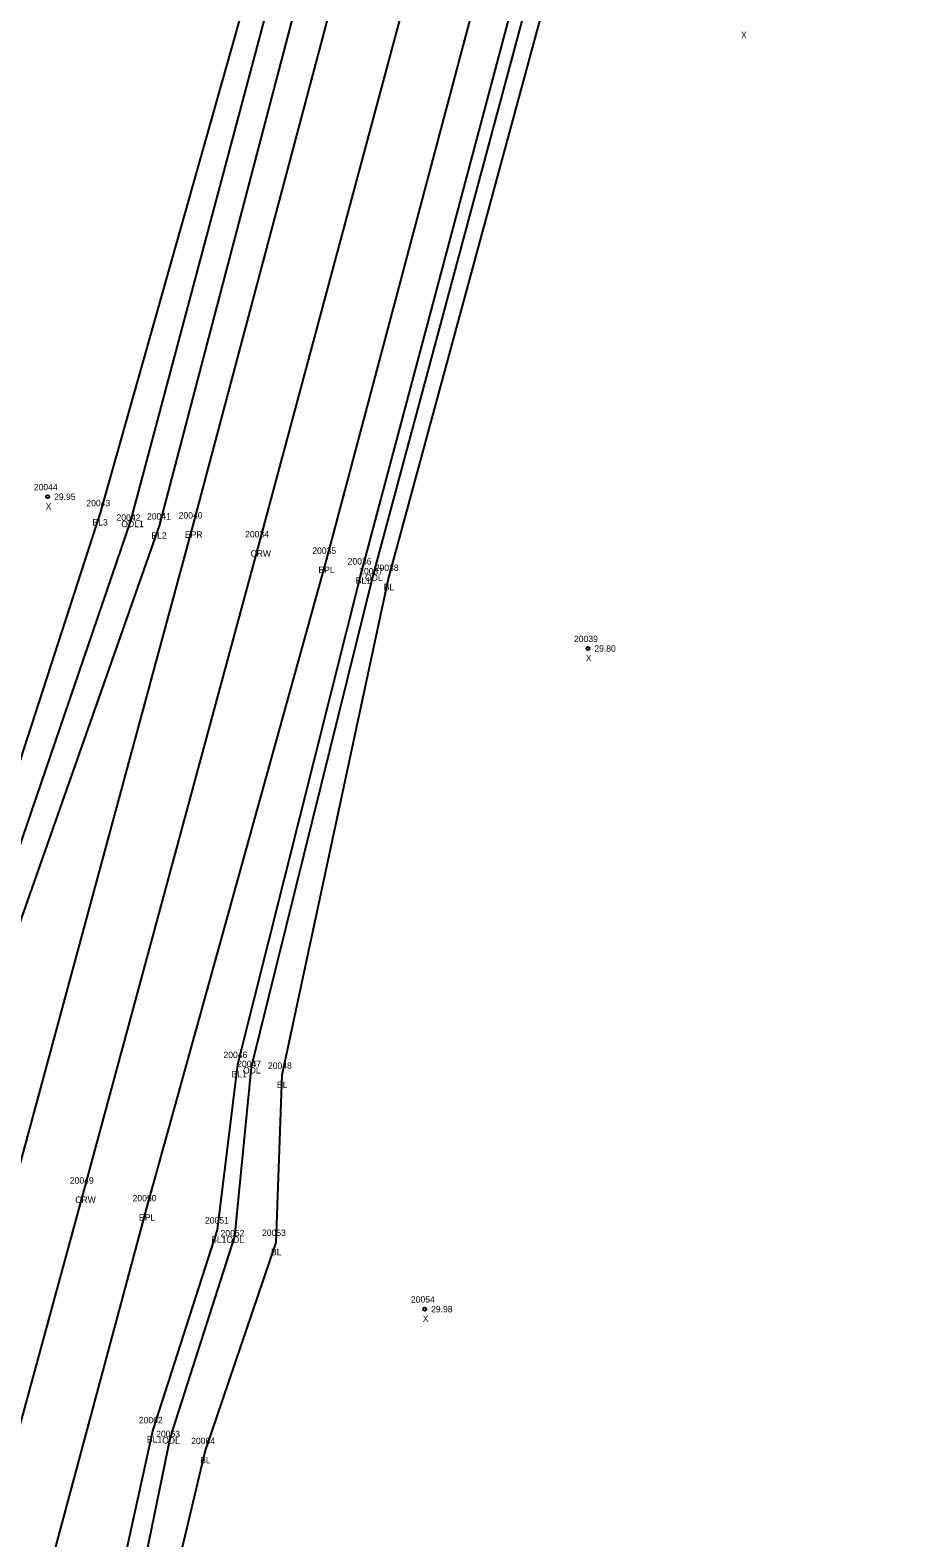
# Model space of a CAD drawing. Extents: x 2432729 to 2433340, y 684958 to 688103.
# Drawn here: x 2433024.5 to 2433161.1, y 687632.9 to 687867.9 of the extents above; entities that cross this region are included whole.
import ezdxf

# ---------------------------------------------------------------- set-up
doc = ezdxf.new("R2010")
doc.units = 0
for name, color, linetype in [('RD_DTM_BkLn1', 7, 'Continuous'), ('RD_EX_H2O', 7, 'Continuous'), ('RD_EX_H2O_txCode', 7, 'Continuous'), ('RD_EX_Road', 7, 'Continuous'), ('RD_EX_Road_txCode', 7, 'Continuous'), ('RD_Sketch8', 7, 'Continuous'), ('RD_SMD_Locator', 7, 'Continuous'), ('RD_SMD_Misc', 7, 'Continuous')]:
    doc.layers.add(name, color=color, linetype=linetype)

msp = doc.modelspace()

# ---------------------------------------------------------------- linework, layer by layer
at = {"layer": 'RD_DTM_BkLn1'}
for points in [[(2433118.26, 688093.2), (2433092.06, 687992.21), (2433063.59, 687892.57), (2433035.4, 687792.67), (2433003.26, 687693.63), (2432973.78, 687591.87), (2432942.45, 687477.63), (2432922.14, 687395), (2432910.39, 687336.67), (2432899.1, 687275.13), (2432892.65, 687218), (2432891.75, 687172.49)], [(2433125.46, 688091.48), (2433098.1, 687989.98), (2433070.67, 687890.07), (2433044.57, 687790.6), (2433009.89, 687691.98), (2432980.82, 687589.28), (2432951.34, 687483.95), (2432927.37, 687394.4), (2432914.6, 687336.1), (2432907.58, 687275.27), (2432904.68, 687217.27), (2432900.37, 687172.96), (2432891.75, 687172.49)], [(2433140.82, 688087.65), (2433112.94, 687984.39), (2433086.23, 687884.97), (2433060.15, 687787.81), (2433032.83, 687687.07), (2433004.93, 687584.9), (2432976.21, 687475.71), (2432953.67, 687387.58), (2432941.78, 687332.31), (2432932.37, 687274.14), (2432926.02, 687213.66), (2432924.35, 687158.94)], [(2433156.54, 688084.3), (2433128.42, 687980.72), (2433101.84, 687880.23), (2433076.15, 687783.58), (2433056.79, 687706.65), (2433053.61, 687680.85), (2433043.6, 687649.71), (2433027.96, 687578.58), (2432999.4, 687470.47), (2432976.82, 687380.76), (2432967.08, 687327.52), (2432956.82, 687270.44), (2432953.12, 687234.52), (2432952.13, 687211.69)], [(2433161.14, 688083.06), (2433133.45, 687979.3), (2433106.44, 687878.75), (2433080.34, 687782.58), (2433063.71, 687704.97), (2433062.78, 687678.91), (2433051.75, 687646.46), (2433035.42, 687577.73), (2433004.6, 687469.86), (2432982.67, 687378.73), (2432971.98, 687326.06), (2432962.83, 687268.71), (2432961.78, 687241.18), (2432987.4, 687248.62)]]:
    msp.add_lwpolyline(points, dxfattribs=at)
at = {"layer": 'RD_EX_H2O'}
for points in [[(2433122.48, 688092.22), (2433094.03, 687991.07), (2433066.93, 687892.02), (2433040.1, 687791.41), (2433006.23, 687692.29), (2432977.32, 687590.19), (2432946.52, 687480.52), (2432925.1, 687394.47), (2432912.11, 687336.21), (2432903.51, 687275.66), (2432898.99, 687217.48), (2432895.84, 687179.01)], [(2433158.82, 688083.82), (2433130.6, 687980.05), (2433103.89, 687879.65), (2433077.93, 687783.05), (2433058.91, 687706.24), (2433056.32, 687679.85), (2433046.3, 687648.55), (2433031.84, 687578.12), (2433002.04, 687470.32), (2432979.46, 687380.11), (2432969.67, 687326.76), (2432959.16, 687269.46), (2432956.03, 687234.5)]]:
    msp.add_lwpolyline(points, dxfattribs=at)
at = {"layer": 'RD_EX_Road'}
for points in [[(2433130.63, 688090.22), (2433103.18, 687988.73), (2433075.68, 687887.89), (2433049.83, 687790.75), (2433022.33, 687689.17), (2432994.76, 687586.82), (2432966.23, 687480.17), (2432943.15, 687390.42), (2432931.4, 687334.3), (2432921.83, 687273.88), (2432915.64, 687215.4), (2432913.86, 687159.12)], [(2433151.11, 688085.43), (2433123.35, 687982.08), (2433096.36, 687882.07), (2433070.62, 687785.25), (2433042.64, 687684.31), (2433015.24, 687582.49), (2432986.34, 687474.01), (2432964, 687384.38), (2432952.4, 687330.76), (2432943.09, 687273.42), (2432937.12, 687213.43), (2432935.51, 687158.7)]]:
    msp.add_lwpolyline(points, dxfattribs=at)
at = {"layer": 'RD_SMD_Locator'}
for centre, radius in [((2433027.21, 687795.16), 0.25), ((2433035.4, 687792.67), 0.001), ((2433040.1, 687791.41), 0.001), ((2433044.57, 687790.6), 0.001), ((2433049.83, 687790.75), 0.001), ((2433060.15, 687787.81), 0.001), ((2433070.62, 687785.25), 0.001), ((2433076.15, 687783.58), 0.001), ((2433077.93, 687783.05), 0.001), ((2433080.34, 687782.58), 0.001), ((2433111.42, 687771.5), 0.25), ((2433056.79, 687706.65), 0.001), ((2433058.91, 687706.24), 0.001), ((2433063.71, 687704.97), 0.001), ((2433032.83, 687687.07), 0.001), ((2433042.64, 687684.31), 0.001), ((2433053.61, 687680.85), 0.001), ((2433056.32, 687679.85), 0.001), ((2433062.78, 687678.91), 0.001), ((2433085.98, 687668.51), 0.25), ((2433043.6, 687649.71), 0.001), ((2433046.3, 687648.55), 0.001), ((2433051.75, 687646.46), 0.001)]:
    msp.add_circle(centre, radius, dxfattribs=at)

# ---------------------------------------------------------------- texts
at = {"layer": 'RD_EX_H2O_txCode'}
for s, p in [('20042', (2433037.94, 687791.41)), ('ODL1', (2433038.69, 687790.41)), ('20037', (2433075.77, 687783.05)), ('ODL', (2433076.68, 687782.05)), ('20047', (2433056.75, 687706.24)), ('ODL', (2433057.66, 687705.24)), ('20052', (2433054.16, 687679.85)), ('ODL', (2433055.07, 687678.85)), ('20063', (2433044.12, 687648.55)), ('ODL', (2433045.06, 687647.55))]:
    msp.add_text(s, height=1, dxfattribs=at).set_placement(p)
at = {"layer": 'RD_EX_Road_txCode'}
for s, p in [('20040', (2433047.63, 687791.75)), ('EPR', (2433048.6, 687788.75)), ('20035', (2433068.46, 687786.25)), ('EPL', (2433069.41, 687783.25)), ('20050', (2433040.45, 687685.31)), ('EPL', (2433041.44, 687682.31))]:
    msp.add_text(s, height=1, dxfattribs=at).set_placement(p)
at = {"layer": 'RD_Sketch8'}
for s, p in [('X', (2433135.29, 687866.65)), ('20044', (2433025.05, 687796.16)), ('X', (2433026.9, 687793.16)), ('29.95', (2433028.21, 687794.66)), ('20039', (2433109.26, 687772.5)), ('X', (2433111.11, 687769.5)), ('29.80', (2433112.42, 687771)), ('20054', (2433083.83, 687669.51)), ('29.98', (2433086.98, 687668.01)), ('X', (2433085.67, 687666.51))]:
    msp.add_text(s, height=1, dxfattribs=at).set_placement(p)
at = {"layer": 'RD_SMD_Misc'}
for s, p in [('20043', (2433033.24, 687793.67)), ('BL3', (2433034.19, 687790.67)), ('20041', (2433042.7, 687791.6)), ('BL2', (2433043.37, 687788.6)), ('20034', (2433057.99, 687788.81)), ('CRW', (2433058.83, 687785.81)), ('20036', (2433073.97, 687784.58)), ('20038', (2433078.19, 687783.58)), ('BL1', (2433075.23, 687781.58)), ('BL', (2433079.59, 687780.58)), ('20046', (2433054.61, 687707.65)), ('20048', (2433061.55, 687705.97)), ('BL1', (2433055.87, 687704.65)), ('BL', (2433062.95, 687702.97)), ('20049', (2433030.67, 687688.07)), ('CRW', (2433031.51, 687685.07)), ('20051', (2433051.73, 687681.85)), ('20053', (2433060.62, 687679.91)), ('BL1', (2433052.69, 687678.85)), ('BL', (2433062.03, 687676.91)), ('20062', (2433041.42, 687650.71)), ('BL1', (2433042.68, 687647.71)), ('20064', (2433049.57, 687647.46)), ('BL', (2433050.99, 687644.46))]:
    msp.add_text(s, height=1, dxfattribs=at).set_placement(p)

doc.saveas('drawing.dxf')
